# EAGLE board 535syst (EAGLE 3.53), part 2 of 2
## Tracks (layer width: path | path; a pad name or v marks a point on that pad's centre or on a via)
+12V  (via drill 0.61 pad 1.02)
  Top 0.406: 51.73,7.76 51.73,28.72 51.09,29.35 47.28,29.35 46.65,29.98 v46.65,43.64 | v26.01,47.76 26.01,44.27 25.37,43.64 24.74,43.64
  Bottom 0.406: 24.74,43.64 27.28,43.64 33.95,43.64 34.26,43.96 36.49,43.96 36.8,43.64 v46.65,43.64 | D2. 24.74,66.82 24.1,67.45 20.93,67.45 | D2. 24.74,48.4 25.37,47.76 v26.01,47.76 | D2. 22.83,63.64 22.2,63 U$2. 22.2,55.7
A0  (via drill 0.61 pad 1.02)
  Top 0.254: 133.32,4.27 133.32,16.33 132.37,17.29 132.37,21.09 133.32,22.05 133.32,24.27 132.37,25.22 132.37,38.87 133.32,39.83 | 97.76,4.27 94.59,4.27 93.95,4.9 93.95,11.57 93.32,12.21 v93.32,22.05 93.32,34.11 93.95,34.75 v93.95,41.42 | v89.19,44.59 89.19,45.54 88.56,46.18 86.33,46.18 84.43,44.27 75.22,44.27 73.32,46.18 55.85,46.18 54.9,47.13 54.9,60.15 54.27,60.78 48.23,60.78 | v129.51,83.64 129.51,74.75 128.88,74.12 128.88,59.83 127.29,58.24 127.29,41.73 v127.61,41.42
  Bottom 0.254: 133.32,4.27 133.32,4.9 132.69,5.54 104.75,5.54 103.48,4.27 97.76,4.27 | v93.32,22.05 87.6,22.05 | v89.19,44.59 89.19,41.73 93.64,41.73 v93.95,41.42 | v127.61,41.42 131.74,41.42 133.32,39.83 | v129.51,83.64 130.15,83.01 134.59,83.01
A1  (via drill 0.61 pad 1.02)
  Top 0.254: 130.78,4.27 130.78,16.33 129.83,17.29 129.83,21.09 130.78,22.05 131.1,22.36 131.1,34.43 131.74,35.07 131.74,38.87 130.78,39.83 130.78,41.1 131.42,41.73 132.05,41.73 132.69,42.37 132.69,53.16 132.37,53.48 132.37,84.91 133.01,85.55 134.59,85.55 | v101.89,18.24 101.89,4.9 102.53,4.27 105.38,4.27 | v54.27,46.18 54.27,48.72 53.63,49.35 46.33,49.35 45.69,49.99 45.69,60.78 | v51.09,43.64 50.46,43.64 49.82,43 v49.82,36.97 | v45.06,19.19 v45.06,36.97 | v86.65,15.7 86.33,16.01 86.33,18.87 86.97,19.51 87.6,19.51
  Bottom 0.254: v101.89,18.24 93,18.24 91.73,19.51 87.6,19.51 | v54.27,46.18 51.73,46.18 51.09,45.54 v51.09,43.64 | v45.06,36.97 v49.82,36.97 | v45.06,19.19 60.3,19.19 60.93,18.56 60.93,16.33 61.57,15.7 v86.65,15.7 | 130.78,4.27 130.78,3.31 130.15,2.68 108.88,2.68 107.29,4.27 105.38,4.27
A2  (via drill 0.61 pad 1.02)
  Top 0.254: 128.24,4.27 v128.24,13.16 128.24,16.33 127.29,17.29 127.29,20.14 128.24,21.09 128.24,22.05 127.93,22.36 127.93,34.43 127.29,35.07 127.29,39.83 | 127.29,39.83 128.24,39.83 | 48.23,63.32 46.96,64.59 44.42,64.59 43.79,65.23 v43.79,89.68 | v73.63,89.68 73.63,82.69 74.27,82.05 v79.67,82.05 | v97.13,82.37 97.45,82.69 97.45,91.26 98.08,91.9 102.84,91.9 104.11,93.17 v105.7,93.17 | v128.88,88.09 128.88,91.26 128.24,91.9 126.34,91.9 125.7,92.53 v125.7,94.12 125.39,94.44 123.48,94.44 122.85,93.8 122.85,77.29 123.48,76.66 124.75,76.66 125.7,75.71 125.7,74.44 126.66,73.48 126.66,40.46 127.29,39.83
  Bottom 0.254: v128.24,13.16 98.4,13.16 97.76,12.52 97.76,11.89 | v73.63,89.68 v43.79,89.68 | v97.13,82.37 80.3,82.37 79.98,82.05 v79.67,82.05 | v105.7,93.17 108.24,93.17 109.51,94.44 125.39,94.44 v125.7,94.12 | v128.88,88.09 134.59,88.09
A3  (via drill 0.61 pad 1.02)
  Top 0.254: 125.7,4.27 v125.7,11.89 125.7,16.33 124.75,17.29 124.75,20.14 125.7,21.09 125.7,22.05 124.75,23 124.75,38.87 125.7,39.83 v125.7,51.26 | 45.69,63.32 45.69,62.69 46.33,62.05 51.41,62.05 52.04,62.69 v52.04,69.35 | v73.95,69.35 73.95,74.12 74.59,74.75 79.03,74.75 79.67,75.39 v80.62,75.39 | 134.59,90.63 132.37,90.63 131.74,89.99 131.74,75.39 131.42,75.07 v131.42,73.48 131.42,71.9 131.74,71.58 v131.74,51.26
  Bottom 0.254: v125.7,11.89 105.38,11.89 | v52.04,69.35 v73.95,69.35 | v80.62,75.39 97.45,75.39 98.08,74.75 115.86,74.75 116.18,74.44 116.18,73.8 116.5,73.48 v131.42,73.48 | v131.74,51.26 v125.7,51.26
A4  (via drill 0.61 pad 1.02)
  Top 0.254: 123.16,4.27 123.16,16.33 122.21,17.29 122.21,20.46 123.16,21.41 123.16,22.05 v123.16,29.35 123.16,34.43 122.21,35.38 122.21,38.87 123.16,39.83 | v103.8,14.43 103.8,15.06 104.43,15.7 106.65,15.7 107.29,16.33 107.29,28.72 106.65,29.35 105.38,29.35 | 48.23,65.86 49.82,64.28 v50.14,64.28 | v75.86,45.22 v75.86,63 | v91.1,30.62 91.41,30.94 91.41,38.56 91.1,38.87 91.1,42.05 v91.73,42.68
  Bottom 0.254: 97.76,14.43 v103.8,14.43 | v50.14,64.28 53.95,64.28 54.9,65.23 72.36,65.23 73,64.59 73,63.64 73.63,63 v75.86,63 | v75.86,45.22 86.02,45.22 86.97,46.18 88.87,46.18 90.14,44.91 91.1,44.91 91.73,44.27 v91.73,42.68 | v91.1,30.62 98.4,30.62 99.03,29.98 104.75,29.98 105.38,29.35 v123.16,29.35
A5  (via drill 0.61 pad 1.02)
  Top 0.254: 120.62,4.27 v120.62,14.43 120.62,16.33 119.67,17.29 119.67,20.46 120.62,21.41 120.62,22.05 120.62,34.11 119.67,35.07 119.67,38.87 120.62,39.83 | v73.63,52.53 74.27,51.89 v74.27,47.76 | v96.49,48.08 96.49,40.15 97.13,39.51 97.76,39.51
  Bottom 0.254: v120.62,14.43 105.38,14.43 | v73.63,52.53 44.42,52.53 43.79,53.16 43.79,65.23 44.42,65.86 45.69,65.86 | v74.27,47.76 84.75,47.76 85.7,48.72 87.92,48.72 88.56,48.08 v96.49,48.08 96.49,43.96 97.13,43.32 98.08,43.32 99.03,42.37 102.53,42.37 104.11,40.78 119.99,40.78 120.62,40.15 120.62,39.83
A6  (via drill 0.61 pad 1.02)
  Top 0.254: 118.08,4.27 118.08,16.33 117.13,17.29 117.13,20.46 118.08,21.41 118.08,22.05 118.08,34.11 117.13,35.07 117.13,39.51 117.45,39.83 | 117.45,39.83 118.08,39.83 | v77.13,63.96 77.13,61.74 76.49,61.1 76.49,50.94 v76.81,50.62 | 117.45,39.83 117.45,50.62 v117.13,50.94
  Bottom 0.254: 118.08,22.05 118.08,22.68 117.45,23.32 102.84,23.32 101.57,22.05 97.76,22.05 | v77.13,63.96 74.59,63.96 72.68,65.86 53.63,65.86 53,65.23 49.5,65.23 48.87,64.59 47.6,64.59 46.96,65.23 46.96,66.5 46.33,67.13 44.42,67.13 43.79,67.77 43.79,69.04 44.42,69.67 47.6,69.67 48.23,69.04 48.23,68.4 | v76.81,50.62 80.3,50.62 81.57,51.89 94.27,51.89 94.59,52.21 97.76,52.21 98.4,51.57 103.48,51.57 104.11,50.94 v117.13,50.94
A7  (via drill 0.61 pad 1.02)
  Top 0.254: 115.54,4.27 115.54,16.33 114.59,17.29 114.59,20.46 115.54,21.41 115.54,22.05 115.54,33.79 114.59,34.75 114.59,39.83 | 114.59,39.83 115.54,39.83 | v97.45,67.13 97.45,57.61 97.76,57.29 | v114.59,53.48 114.59,39.83
  Bottom 0.254: 115.54,22.05 115.54,21.73 114.91,21.09 106.34,21.09 105.38,22.05 | v97.45,67.13 47.6,67.13 46.33,68.4 45.69,68.4 | v114.59,53.48 108.24,53.48 105.7,56.02 98.4,56.02 97.76,56.65 97.76,57.29
A8  (via drill 0.61 pad 1.02)
  Top 0.254: 118.08,19.51 119.04,20.46 v119.04,34.43 118.08,35.38 118.08,37.29 119.04,38.24 119.04,44.59 118.08,45.54 118.08,55.07 | v95.54,69.99 95.54,64.91 96.49,63.96 96.49,63
  Bottom 0.254: 96.49,63 96.49,60.78 122.21,60.78 122.85,60.15 122.85,57.29 122.21,56.65 118.72,56.65 118.08,56.02 118.08,55.07 | v95.54,69.99 82.52,69.99 82.21,69.67 75.54,69.67 74.27,68.4 51.73,68.4 50.77,69.35 50.77,70.31 50.14,70.94 48.23,70.94 | v119.04,34.43 105.38,34.43
A9  (via drill 0.61 pad 1.02)
  Top 0.254: 121.58,37.29 v121.58,31.89 121.58,20.46 120.62,19.51 | 121.58,37.29 120.62,37.29 | 121.58,37.29 121.58,44.91 120.62,45.86 120.62,55.07 120.62,67.13 119.99,67.77 115.54,67.77 114.91,68.4 v114.91,69.67 | v96.49,71.58 96.49,65.55
  Bottom 0.254: v121.58,31.89 105.38,31.89 | 45.69,70.94 45.69,71.58 46.33,72.21 52.68,72.21 53,71.9 75.22,71.9 75.54,71.58 v96.49,71.58 96.49,70.31 97.13,69.67 105.07,69.67 105.7,70.31 107.29,70.31 107.61,69.99 114.59,69.99 v114.91,69.67
A10  (via drill 0.61 pad 1.02)
  Top 0.254: 128.88,37.29 128.88,23.95 129.2,23.63 129.2,20.46 128.24,19.51 | 128.88,37.29 128.24,37.29 | v108.24,57.61 107.92,57.93 107.92,58.88 107.61,59.19 107.61,63.32 v107.92,63.64 | v51.73,73.16 v51.73,70.94 | v74.9,70.94 74.9,73.48 75.54,74.12 v79.67,74.12 | v94.59,74.44 94.59,68.4 94.91,68.08 v94.91,63.96 | 128.88,37.29 129.2,37.61 129.2,43 128.56,43.64 128.56,54.75 128.24,55.07
  Bottom 0.254: 105.38,36.97 105.38,36.02 106.02,35.38 126.34,35.38 128.24,37.29 | v108.24,57.61 107.92,57.93 107.92,58.88 107.29,59.51 99.99,59.51 99.35,58.88 95.54,58.88 94.91,59.51 v94.91,63.96 97.13,63.96 97.76,63.32 98.72,63.32 99.03,63 | v107.92,63.64 108.24,63.96 111.42,63.96 112.05,63.32 112.05,62.05 112.69,61.42 115.23,61.42 115.86,62.05 141.26,62.05 141.9,61.42 141.9,54.75 141.26,54.11 128.88,54.11 128.24,54.75 128.24,55.07 | v51.73,73.16 51.41,73.48 48.23,73.48 | v51.73,70.94 52.04,71.26 74.59,71.26 v74.9,70.94 | v79.67,74.12 94.27,74.12 v94.59,74.44
A11  (via drill 0.61 pad 1.02)
  Top 0.254: 123.16,19.51 124.12,20.46 124.12,34.43 123.16,35.38 123.16,37.29 124.12,38.24 124.12,40.15 123.8,40.46 123.8,45.54 123.16,46.18 123.16,55.07 | v100.62,39.51 100.62,41.1 100.94,41.42 100.94,56.34 101.57,56.97 v101.57,63 101.57,65.55 | 45.69,73.48 46.96,72.21 48.87,72.21 49.5,71.58 49.5,66.5 v49.82,66.18
  Bottom 0.254: v100.62,39.51 105.38,39.51 105.7,39.83 109.19,39.83 110.15,38.87 122.53,38.87 123.16,38.24 123.16,37.29 | v49.82,66.18 50.14,66.5 96.81,66.5 97.76,65.55 97.76,64.59 98.4,63.96 99.67,63.96 100.62,63 v101.57,63
A12  (via drill 0.61 pad 1.02)
  Top 0.254: 113,4.27 113,16.01 112.05,16.97 112.05,20.46 113,21.41 113,22.05 113,33.79 112.05,34.75 112.05,38.87 113,39.83 v113,44.59 | v103.48,63.96 103.48,49.04 104.11,48.4 106.02,48.4 106.65,47.76 106.65,45.22 106.02,44.59 105.38,44.59 | v50.46,68.08 50.46,75.39 49.82,76.02 48.23,76.02
  Bottom 0.254: v103.48,63.96 100.62,63.96 99.03,65.55 98.4,66.18 98.4,67.45 97.76,68.08 82.52,68.08 81.57,69.04 75.86,69.04 74.59,67.77 50.77,67.77 v50.46,68.08 | v113,44.59 105.38,44.59
A13  (via drill 0.61 pad 1.02)
  Top 0.254: 115.54,19.51 116.5,20.46 116.5,33.79 115.54,34.75 115.54,37.29 116.5,38.24 116.5,44.27 115.54,45.22 v115.54,47.13 115.54,55.07 | 105.38,47.13 103.48,47.13 102.84,47.76 102.84,56.65 102.53,56.97 102.53,67.13 101.57,68.08 100.62,69.04 100.62,71.26 99.99,71.9 v99.67,71.9
  Bottom 0.254: v99.67,71.9 97.76,71.9 97.13,72.53 94.59,72.53 94.27,72.21 75.86,72.21 75.54,72.53 60.93,72.53 60.3,73.16 60.3,74.12 59.66,74.75 46.33,74.75 45.69,75.39 45.69,76.02 | 105.38,47.13 v115.54,47.13
A14  (via drill 0.61 pad 1.02)
  Top 0.254: 109.51,22.05 109.51,5.22 110.46,4.27 | 109.51,22.05 110.46,22.05 | v113,49.67 113,55.07 | v104.43,61.74 104.11,61.42 104.11,50.3 104.75,49.67 105.38,49.67 107.61,49.67 108.24,49.04 108.24,46.18 107.92,45.86 107.92,22.68 108.56,22.05 109.51,22.05 | v53,70.31 53,77.93 52.36,78.56 48.23,78.56 | v73,70.31 73,76.02 73.63,76.66 v79.67,76.66 | v97.45,76.66 97.45,69.67 99.03,68.08
  Bottom 0.254: 105.38,49.67 v113,49.67 | v104.43,61.74 104.43,65.86 103.8,66.5 101.26,66.5 100.94,66.18 99.67,66.18 99.03,66.82 99.03,68.08 | v73,70.31 v53,70.31 | v97.45,76.66 v79.67,76.66
A15  (via drill 0.61 pad 1.02)
  Top 0.254: v108.24,70.94 108.24,65.86 106.97,64.59 106.97,58.24 107.29,57.93 107.29,52.85 106.65,52.21 105.38,52.21 | v72.68,88.72 72.68,80.15 73.32,79.52 79.67,79.52 80.3,78.88 v80.3,77.93 | v100.62,77.29 100.62,72.85 101.57,71.9 101.57,70.63 | J3. v45.69,88.72
  Bottom 0.254: v108.24,70.94 105.07,70.94 104.75,70.63 101.57,70.63 | v45.69,88.72 v72.68,88.72 | v80.3,77.93 80.62,77.61 98.08,77.61 98.4,77.29 v100.62,77.29
ALE  (via drill 0.61 pad 1.02)
  Top 0.254: v95.86,74.44 95.86,74.75 95.22,75.39 93.95,75.39 93.32,74.75 93.32,68.08 93,67.77 v93,58.24 | v94.91,58.24 94.59,57.93 94.59,56.02 94.91,55.7 v94.91,51.26 | v107.29,48.4 107.29,31.25 106.65,30.62 104.75,30.62 104.11,29.98 v104.11,28.4 | v96.81,28.08 97.13,28.08 97.76,27.45 97.76,24.59
  Bottom 0.254: v95.86,74.44 96.18,74.12 100.62,74.12 101.57,73.16 | v94.91,58.24 v93,58.24 | v94.91,51.26 95.22,50.94 98.4,50.94 99.03,50.3 102.84,50.3 104.75,48.4 v107.29,48.4 | v96.81,28.08 103.8,28.08 v104.11,28.4
CS_E^2  (via drill 0.61 pad 1.02)
  Top 0.254: v100.3,58.56 100.3,43 99.67,42.37 99.03,42.37 98.4,43 98.4,43.96 97.76,44.59
  Bottom 0.254: v100.3,58.56 106.65,58.56 107.29,57.93 107.29,55.39 108.56,54.11 113.32,54.11 113.64,54.43 114.91,54.43 115.86,53.48 145.07,53.48 145.39,53.8 148.56,53.8
CS_PIO  (via drill 0.61 pad 1.02)
  Top 0.254: v94.27,45.22 94.27,43.32 93,42.05 93,38.87 92.68,38.56 92.68,23.63 92.05,23 92.05,17.6 91.41,16.97 89.51,16.97 88.87,16.33 88.87,15.06 88.24,14.43 87.6,14.43
  Bottom 0.254: v94.27,45.22 94.27,42.68 94.91,42.05 97.76,42.05
CS_PROM  (via drill 0.61 pad 1.02)
  Top 0.254: v98.72,53.48 99.03,53.16 99.03,47.76 98.4,47.13 97.76,47.13 | v130.78,52.53 130.78,55.07
  Bottom 0.254: v130.78,52.53 107.92,52.53 106.97,53.48 v98.72,53.48
CS_RAM  (via drill 0.61 pad 1.02)
  Top 0.254: v99.67,30.94 99.67,33.79 99.03,34.43 97.76,34.43 | v142.53,30.62 142.53,44.91 v141.9,45.54
  Bottom 0.254: v99.67,30.94 99.99,30.62 v142.53,30.62 | v141.9,45.54 142.53,46.18 148.56,46.18
CS_RTC  (via drill 0.61 pad 1.02)
  Top 0.254: v104.11,45.86 104.11,43.32 105.38,42.05 | v134.28,45.86 134.28,72.85 133.32,73.8 133.32,77.29 133.96,77.93 134.59,77.93
  Bottom 0.254: v104.11,45.86 v134.28,45.86
GND  (via drill 0.61 pad 1.02)
  Top 0.406: 24.74,46.18 v14.58,46.18 7.91,46.18 7.28,45.54 7.28,21.41 6.64,20.78 6.01,20.78 | 30.77,77.61 30.77,84.91 30.14,85.55 16.48,85.55 15.85,84.91 15.85,80.79 16.48,80.15 17.12,80.15 17.12,77.61 18.39,76.34 C12. | v92.37,73.16 92.37,66.5 91.41,65.55 | v105.38,62.69 105.7,62.37 105.7,57.61 105.38,57.29 | 107.92,72.85 108.56,72.85 109.51,71.9 109.51,63 109.19,62.69 | R1. 156.18,62.69 155.55,63.32 155.55,66.5 154.6,67.45 154.6,77.29 153.96,77.93 151.1,77.93 | 143.48,39.83 143.48,49.99 142.53,50.94 142.53,63.32 143.17,63.96 BAT1. | v121.26,96.98 120.62,96.34 120.62,84.28 120.94,83.96 120.94,83.33 v121.26,83.01 121.58,82.69 121.58,77.61 121.26,77.29 121.26,69.35 120.62,68.72 118.72,68.72 118.08,69.35 118.08,72.21 117.45,72.85 C15. | C16. 90.46,32.84 90.46,43.64 90.46,46.18 90.46,49.99 v90.46,53.16 | v105.38,27.76 105.38,24.59 | 95.22,14.43 95.54,14.74 95.54,22.36 96.49,23.32 96.49,26.49 95.54,27.45 C7. | 143.48,4.27 143.48,16.33 142.21,17.6 142.21,20.14 143.48,21.41 143.48,22.05 v143.48,27.76
  Bottom 0.254: 94.59,29.03 95.22,28.4 C7.
  Bottom 0.406: 6.01,20.78 6.01,18.87 6.64,18.24 15.21,18.24 16.48,16.97 17.75,15.7 17.75,2.36 | 24.74,46.18 27.28,46.18 27.91,46.81 53,46.81 53.63,47.45 53.63,50.62 54.27,51.26 74.59,51.26 75.22,51.89 75.22,53.8 | 15.85,2.36 17.75,2.36 | 17.75,2.36 46.33,2.36 46.65,2.68 | C13. 30.14,73.8 30.77,74.44 30.77,77.61 | X2. 5.69,79.52 6.32,80.15 17.12,80.15 | C12. 15.21,67.45 14.58,66.82 14.58,63.64 v14.58,46.18 | v92.37,73.16 99.03,73.16 99.99,73.16 101.26,71.9 106.97,71.9 107.92,72.85 109.19,71.58 113.32,71.58 113.96,72.21 114.91,72.21 C15. | 109.19,62.69 108.88,62.37 105.7,62.37 v105.38,62.69 | 156.18,62.69 154.6,64.28 143.8,64.28 BAT1. | 151.1,77.93 151.1,78.56 150.47,79.2 143.48,79.2 142.85,79.83 137.77,79.83 137.13,80.47 137.13,81.1 136.5,81.74 129.2,81.74 128.24,82.69 128.24,83.64 127.61,84.28 126.34,84.28 125.07,83.01 124.43,83.01 v121.26,83.01 | v121.26,96.98 118.08,96.98 | 87.6,16.97 91.41,16.97 92.05,16.33 92.05,15.06 92.68,14.43 95.22,14.43 | 75.22,53.8 C10. | 75.22,53.8 79.03,53.8 M1. v90.46,53.16 | 94.59,29.03 90.46,29.03 89.83,29.67 89.83,32.21 C16. | C7. 95.86,26.81 97.76,26.81 98.08,27.13 104.75,27.13 v105.38,27.76 v143.48,27.76 145.07,27.76 | 143.48,4.27 143.48,2.36 142.85,1.73 105.38,1.73 | 145.07,27.76 148.56,27.76 | 145.07,27.76 145.07,39.19 144.44,39.83 143.48,39.83
INT0  (via drill 0.61 pad 1.02)
  Top 0.254: v72.05,93.17 71.73,92.85 71.73,69.04 72.36,68.4 74.59,68.4 75.54,69.35 77.44,69.35 78.71,70.63
  Bottom 0.254: v72.05,93.17 71.41,93.8 59.98,93.8 59.35,94.44
INT1  (via drill 0.61 pad 1.02)
  Top 0.254: 76.17,68.08 76.49,68.08 77.13,67.45 77.13,65.23 76.49,64.59 67.92,64.59 67.28,65.23 v67.28,85.55 67.28,92.21 66.65,92.85 63.47,92.85 62.84,93.49 62.84,96.34 62.2,96.98 J4.
  Bottom 0.254: v67.28,85.55 74.59,85.55 75.86,84.28 79.67,84.28 80.3,83.64 97.13,83.64 99.03,81.74 102.21,81.74 102.53,81.42 103.8,81.42 104.11,81.74 112.37,81.74 113,81.1 113,80.47
MODE  (via drill 0.61 pad 1.02)
  Top 0.254: v99.35,43.64 99.67,43.96 99.67,54.11 99.03,54.75 97.76,54.75 | 148.56,16.33 154.28,16.33 154.91,16.97 154.91,39.19 156.18,40.46 156.18,43.64
  Bottom 0.254: v99.35,43.64 99.67,43.32 106.65,43.32 107.29,42.68 146.34,42.68 146.66,42.37 155.55,42.37 156.18,43 156.18,43.64
N$1  (via drill 0.61 pad 1.02)
  Top 0.254: v124.43,63.96 124.43,75.39
  Bottom 0.254: C8. 114.91,63.32 117.45,63.32 118.08,63.96 v124.43,63.96
N$2  (via drill 0.61 pad 1.02)
  Top 0.254: 148.56,38.56 150.15,38.56 150.79,39.19 150.79,49.99 151.42,50.62 153.01,50.62 153.64,51.26 R12. v153.64,65.86 | v111.73,66.5 111.73,89.68 111.1,90.31 108.56,90.31 107.92,89.68 R3.
  Bottom 0.254: v153.64,65.86 117.45,65.86 R10. v111.73,66.5
N$3
  Bottom 0.254: 148.56,56.34 151.1,56.34 151.74,55.7 151.74,51.26 153.64,49.35 153.64,43.64
N$4  (via drill 0.61 pad 1.02)
  Top 0.254: v116.5,48.72 116.18,49.04 116.18,52.85 116.5,53.16 116.5,64.28 v115.23,65.55
  Bottom 0.254: v115.23,65.55 107.29,65.55 106.65,66.18 106.65,66.5 | v116.5,48.72 148.56,48.72
N$5
  Top 0.254: 130.78,19.51 131.1,19.51 131.74,18.87 131.74,2.36 132.37,1.73 R13. 145.39,2.36 145.39,16.33 146.66,17.6 146.66,39.19 147.29,39.83 147.29,41.73 147.93,42.37 149.2,42.37 149.83,43 149.83,58.24 149.2,58.88 T3.
N$6  (via drill 0.61 pad 1.02)
  Top 0.254: v145.39,41.42 v145.39,51.26 v145.39,69.04
  Bottom 0.254: v145.39,41.42 135.23,41.42 134.59,40.78 134.59,39.19 133.96,38.56 131.42,38.56 130.78,37.92 130.78,37.29 | v145.39,51.26 T2. | v145.39,69.04 R11.
N$7  (via drill 0.61 pad 1.02)
  Top 0.254: v151.1,82.37 151.1,85.55
  Bottom 0.254: v151.1,82.37 146.02,82.37 144.75,81.1 144.75,80.47
N$8
  Top 0.254: C3. 152.37,80.47 153.01,81.1 153.01,89.99 152.37,90.63 144.75,90.63
N$9
  Top 0.254: R15. 94.59,23.95 94.59,16.33 93.95,15.7 93.95,13.16 95.22,11.89 T4.
  Bottom 0.254: 72.36,14.43 85.06,14.43 86.33,13.16 94.59,13.16 95.22,12.52 T4.
N$10
  Bottom 0.406: 19.66,83.64 19.02,83.64 18.39,83.01 18.39,77.93 17.12,76.66 R7. 17.12,69.35 17.75,68.72 19.02,68.72 19.66,68.08 19.66,66.82 19.02,66.18 17.75,66.18 17.12,65.55 17.12,56.02
N$11
  Bottom 0.254: 144.75,77.93 147.29,77.93
N$12
  Top 0.254: 144.75,83.01 146.66,83.01 147.29,82.37 C1.
N$13
  Bottom 0.254: 144.75,85.55 147.29,85.55
N$14
  Bottom 0.254: 144.75,88.09 C2.
N$15  (via drill 0.61 pad 1.02)
  Top 0.254: v158.09,19.51 v158.09,83.64
  Bottom 0.254: v158.09,83.64 157.45,84.28 143.48,84.28 142.21,85.55 137.13,85.55 | 148.56,19.51 v158.09,19.51
N$16  (via drill 0.61 pad 1.02)
  Top 0.254: 137.13,83.01 137.13,83.96 138.4,85.23 140.94,85.23 141.58,84.6 141.58,60.78 141.9,60.47 v141.9,47.45 | v151.74,47.45 151.74,42.37 153.01,41.1 153.01,22.68 152.37,22.05 148.56,22.05
  Bottom 0.254: v151.74,47.45 v141.9,47.45
N$17
  Bottom 0.254: 16.48,19.51 16.48,20.14 15.85,20.78 8.86,20.78 8.23,21.41 8.23,22.68 7.59,23.32 6.01,23.32 5.37,23.32 4.1,24.59 2.83,24.59 2.2,23.95 2.2,16.97 2.83,16.33 5.05,16.33 5.69,15.7 R6.
N$18
  Top 0.254: 90.14,14.43 92.05,14.43 92.68,13.79 92.68,10.62
N$19  (via drill 0.61 pad 1.02)
  Top 0.254: v119.04,76.02 118.72,76.34 118.72,82.05 118.4,82.37 118.4,83.64 117.77,84.28 114.27,84.28 JP3.
  Bottom 0.254: v119.04,76.02 123.48,76.02 124.12,76.66 129.83,76.66 130.47,76.02 133.96,76.02 134.59,75.39 | R16. JP3.
N$21  (via drill 0.61 pad 1.02)
  Top 0.254: v114.27,55.39 114.27,54.75 113.64,54.11 113.64,51.26 113.96,50.94 113.96,20.46 113,19.51 | v111.42,56.02 111.73,56.34 111.73,58.88
  Bottom 0.254: v114.27,55.39 113.64,56.02 v111.42,56.02
N$22  (via drill 1.93 pad 2.54)
  other vias: 157.45,3
N$23
  Top 0.254: 19.66,69.99 19.66,76.66 18.39,77.93 18.39,83.01 17.75,83.64 JP1.
N$24
  Bottom 0.254: 22.2,83.64 27.6,83.64 28.23,83.01 28.23,70.63 27.6,69.99 22.2,69.99
N$25  (via drill 1.93 pad 2.54)
  other vias: 157.45,96.98
N$26  (via drill 1.93 pad 2.54)
  other vias: 2.51,3
N$27  (via drill 1.93 pad 2.54)
  other vias: 2.51,96.98
N$28  (via drill 2.54 pad 3.81)
  other vias: 6.96,58.56
N$29  (via drill 2.54 pad 3.81)
  other vias: 32.36,58.56
N$34  (via drill 0.61 pad 1.02)
  Top 0.254: v91.73,52.85 91.73,44.91 C5.
  Bottom 0.254: 91.1,57.29 90.78,56.97 84.75,56.97 Q1. | 91.1,57.29 91.1,58.56 91.73,59.19 92.37,59.19 93,59.83 93,64.91 93.64,65.55 93.95,65.55 | v91.73,52.85 92.37,53.48 95.86,53.48 96.49,54.11 96.49,56.65 95.86,57.29 91.1,57.29
N$35  (via drill 0.61 pad 1.02)
  Top 0.254: 93.95,63 v93.95,55.39 93.95,50.62 94.27,50.3 94.27,46.81 93.64,46.18 C6.
  Bottom 0.254: v93.95,55.39 90.46,55.39 90.14,55.07 82.52,55.07 81.25,56.34 79.03,56.34
P00  (via drill 0.61 pad 1.02)
  Top 0.254: v104.11,85.23 104.11,79.83 103.8,79.52 103.8,76.97 104.11,76.66 104.11,75.07 103.48,74.44 102.21,74.44 101.57,75.07 101.57,75.71 | 135.86,4.27 135.86,16.33 134.91,17.29 134.91,21.09 135.86,22.05 135.86,24.27 134.91,25.22 134.91,39.51 135.23,39.83 | 135.23,39.83 135.86,39.83 | v74.27,7.13 74.27,16.33 73.63,16.97 72.36,16.97 | v139.04,84.28 139.04,72.21 138.4,71.58 135.55,71.58 134.91,70.94 134.91,53.8 135.23,53.48 135.23,39.83
  Bottom 0.254: 64.43,21.41 64.43,17.6 65.06,16.97 72.36,16.97 | v104.11,85.23 114.91,85.23 115.86,84.28 125.07,84.28 126.34,85.55 IC10.4 129.83,85.55 131.1,84.28 v139.04,84.28 | 135.86,4.27 135.86,6.81 135.23,7.44 107.29,7.44 106.65,8.08 103.8,8.08 102.53,6.81 97.76,6.81 89.19,6.81 87.92,8.08 85.06,8.08 84.43,7.44 74.59,7.44 v74.27,7.13
P01  (via drill 0.61 pad 1.02)
  Top 0.254: v104.75,77.93 105.07,78.24 105.07,86.5 v105.38,86.82 | 138.4,4.27 138.4,16.33 137.45,17.29 137.45,21.09 138.4,22.05 138.4,24.27 137.45,25.22 137.45,39.83 | 137.45,39.83 138.4,39.83 | v75.22,4.59 75.22,18.87 74.59,19.51 72.36,19.51 | v130.78,57.61 130.78,72.53 130.47,72.85 130.47,86.5 129.83,87.13 128.24,87.13 127.29,88.09 IC10.3 | 137.45,39.83 v137.45,57.61
  Bottom 0.254: J9. 61.89,22.05 62.52,22.68 67.28,22.68 67.92,22.05 67.92,20.14 68.55,19.51 72.36,19.51 | v104.75,77.93 104.75,77.29 104.11,76.66 101.26,76.66 100.3,75.71 99.03,75.71 | v105.38,86.82 126.34,86.82 126.97,87.45 IC10.3 | 138.4,4.27 137.45,3.31 135.23,3.31 134.59,3.95 134.59,6.17 133.96,6.81 105.38,6.81 104.43,6.81 103.16,5.54 85.38,5.54 84.75,4.9 75.54,4.9 v75.22,4.59 | v137.45,57.61 v130.78,57.61
P02  (via drill 0.61 pad 1.02)
  Top 0.254: v109.19,89.36 v109.19,78.88 | 140.94,4.27 v140.94,10.62 140.94,16.33 139.99,17.29 139.99,21.09 140.94,22.05 140.94,24.27 139.99,25.22 139.99,38.87 140.94,39.83 140.94,43 139.99,43.96 v139.99,63 | v76.17,12.84 76.17,21.41 75.54,22.05 72.36,22.05 | v127.93,63 127.93,74.44 128.24,74.75 128.24,86.18 127.61,86.82 126.34,86.82 125.7,87.45 125.7,89.99 126.34,90.63 IC10.2
  Bottom 0.254: 64.43,23.95 68.24,23.95 68.87,23.32 68.87,22.68 69.51,22.05 72.36,22.05 | 101.57,78.24 103.48,78.24 104.11,78.88 v109.19,78.88 | v109.19,89.36 126.34,89.36 126.97,89.99 IC10.2 | v140.94,10.62 104.75,10.62 103.48,9.35 97.76,9.35 97.13,8.71 90.14,8.71 88.24,10.62 87.29,10.62 85.06,12.84 v76.17,12.84 75.86,12.84 | v139.99,63 v127.93,63
P03  (via drill 0.61 pad 1.02)
  Top 0.254: 143.48,19.51 144.44,20.46 144.44,34.11 143.48,35.07 143.48,37.29 144.44,38.24 144.44,55.07 | 144.44,55.07 143.48,55.07 | v83.48,80.15 83.48,69.67 82.84,69.04 80.94,69.04 80.3,68.4 80.3,61.74 80.94,61.1 88.56,61.1 89.19,60.47 v89.19,56.02 | v95.54,56.34 95.86,56.02 98.4,56.02 99.03,56.65 99.03,59.51 v98.72,59.83 | v119.67,63 v119.67,59.83 | 144.44,55.07 144.75,55.39 144.75,66.5 142.85,68.4 142.85,91.26 142.21,91.9 132.69,91.9 131.42,93.17 IC10.1 | v89.19,8.08 84.43,8.08 83.79,8.71 83.79,23.95 83.16,24.59 72.36,24.59
  Bottom 0.254: 61.89,23.95 61.89,24.59 62.52,25.22 68.87,25.22 69.51,24.59 72.36,24.59 | v83.48,80.15 81.25,80.15 80.62,79.52 80.62,78.88 81.25,78.24 99.03,78.24 | v89.19,56.02 89.51,56.34 v95.54,56.34 | v98.72,59.83 99.03,60.15 119.35,60.15 v119.67,59.83 | v119.67,63 125.7,63 126.66,63.96 141.26,63.96 143.48,61.74 143.48,55.07 | 143.48,19.51 143.48,9.98 142.85,9.35 105.38,9.35 104.75,8.71 101.89,8.71 101.26,8.08 v89.19,8.08
P04  (via drill 0.61 pad 1.02)
  Top 0.254: 140.94,19.51 140.94,20.46 141.9,21.41 141.9,24.59 141.26,25.22 141.26,34.11 140.94,34.43 140.94,37.29 141.9,38.24 141.9,43 140.94,43.96 140.94,55.07 | v106.97,80.79 106.97,75.07 105.38,73.48 105.38,64.91 v105.7,64.59 | v136.5,56.65 v136.5,64.91
  Bottom 0.254: 64.43,26.49 71.73,26.49 72.36,27.13 74.9,27.13 75.54,26.49 75.54,21.41 76.17,20.78 85.38,20.78 | 85.38,20.78 85.38,19.19 86.33,18.24 91.73,18.24 93,16.97 97.76,16.97 | v105.7,64.59 116.5,64.59 117.13,65.23 136.18,65.23 v136.5,64.91 | v136.5,56.65 140.31,56.65 140.94,56.02 140.94,55.07 | v106.97,80.79 101.57,80.79 | 85.38,20.78 105.7,20.78 106.02,20.46 116.18,20.46 116.81,21.09 140.31,21.09 140.94,20.46 140.94,19.51
P05  (via drill 0.61 pad 1.02)
  Top 0.254: 138.4,19.51 138.72,19.51 139.36,20.14 139.36,34.11 138.4,35.07 138.4,37.29 139.36,38.24 139.36,43 138.4,43.96 138.4,55.07 v138.4,69.99 | v114.91,79.83 115.54,79.2 115.54,74.44 116.18,73.8 118.08,73.8 118.72,73.16 118.72,70.63 v119.35,69.99 | v103.8,33.48 103.8,31.57 102.84,30.62 102.84,24.91 103.48,24.27 103.48,17.6 104.11,16.97 105.38,16.97
  Bottom 0.254: 61.89,26.49 61.89,27.13 62.52,27.76 68.87,27.76 69.51,28.4 69.51,29.03 70.14,29.67 72.36,29.67 82.21,29.67 82.84,30.3 82.84,32.84 83.48,33.48 88.56,33.48 88.87,33.79 95.86,33.79 96.49,33.16 103.48,33.16 v103.8,33.48 | 99.03,80.79 100.3,80.79 101.26,79.83 111.42,79.83 112.05,79.2 114.27,79.2 v114.91,79.83 | v138.4,69.99 v119.35,69.99 | 138.4,19.51 138.4,17.6 137.77,16.97 105.38,16.97
P06  (via drill 0.61 pad 1.02)
  Top 0.254: 135.86,19.51 136.18,19.51 136.82,20.14 136.82,34.11 135.86,35.07 135.86,37.29 136.82,38.24 136.82,43 135.86,43.96 135.86,55.07 | v117.77,81.74 118.08,81.42 118.08,75.07 v118.4,74.75 | v122.85,74.44 123.48,73.8 123.48,56.97 v123.8,56.65 | v96.81,15.7 96.49,16.01 96.49,18.24 97.76,19.51 | v100.62,35.7 v100.62,19.51
  Bottom 0.254: 64.43,29.03 67.92,29.03 68.55,29.67 68.55,31.57 69.19,32.21 72.36,32.21 80.3,32.21 80.94,32.84 80.94,35.38 81.57,36.02 94.27,36.02 94.59,35.7 v100.62,35.7 | v117.77,81.74 115.54,81.74 114.91,82.37 114.91,83.64 114.27,84.28 107.29,84.28 106.34,83.33 101.57,83.33 | v118.4,74.75 118.72,74.44 v122.85,74.44 | v123.8,56.65 134.28,56.65 135.86,55.07 | v96.81,15.7 108.56,15.7 109.19,16.33 139.04,16.33 139.67,16.97 139.67,19.82 139.04,20.46 136.82,20.46 135.86,19.51 | v100.62,19.51 97.76,19.51
P07  (via drill 0.61 pad 1.02)
  Top 0.254: 133.32,19.51 133.64,19.51 134.28,20.14 134.28,34.11 133.32,35.07 133.32,37.29 134.28,38.24 134.28,42.68 133.32,43.64 133.32,55.07 v133.32,70.94 | v103.16,75.71 v103.16,82.37 | v114.27,70.94 v114.27,75.71 | v101.89,37.29 101.89,32.21 101.26,31.57 101.26,23.63 101.89,23 v101.89,19.51
  Bottom 0.254: 61.89,29.03 61.89,29.67 62.52,30.3 66.65,30.3 67.28,30.94 67.28,34.11 67.92,34.75 72.36,34.75 78.4,34.75 79.03,35.38 79.03,37.92 79.67,38.56 93.64,38.56 93.95,38.24 98.08,38.24 99.03,37.29 v101.89,37.29 | v103.16,82.37 99.99,82.37 99.03,83.33 | v114.27,75.71 v103.16,75.71 | v133.32,70.94 v114.27,70.94 | 133.32,19.51 133.32,18.56 132.69,17.92 109.51,17.92 107.92,19.51 105.38,19.51 v101.89,19.51
P10
  Bottom 0.254: 65.38,53.8 70.46,53.8 71.09,54.43 71.09,56.97 71.73,57.61 89.83,57.61 90.46,58.24 90.46,64.91 89.83,65.55 88.87,65.55
P11
  Bottom 0.254: J8. 62.84,54.43 63.47,55.07 69.82,55.07 70.46,55.7 70.46,57.61 71.09,58.24 88.24,58.24 88.87,58.88 88.87,63
P12
  Bottom 0.254: 65.38,56.34 69.19,56.34 69.82,56.97 69.82,58.24 70.46,58.88 86.97,58.88 87.6,59.51 87.6,64.91 86.97,65.55 86.33,65.55
P13
  Bottom 0.254: 62.84,56.34 62.84,56.97 63.47,57.61 68.55,57.61 69.19,58.24 69.19,58.88 69.82,59.51 85.7,59.51 86.33,60.15 86.33,63
P14
  Bottom 0.254: 65.38,58.88 67.92,58.88 69.19,60.15 84.43,60.15 85.06,60.78 85.06,64.91 84.43,65.55 83.79,65.55
P15
  Bottom 0.254: 62.84,58.88 62.84,59.51 63.47,60.15 67.92,60.15 68.55,60.78 83.16,60.78 83.79,61.42 83.79,63
P16
  Bottom 0.254: 65.38,61.42 81.89,61.42 82.52,62.05 82.52,64.91 81.89,65.55 81.25,65.55
P17
  Bottom 0.254: 62.84,61.42 62.84,62.05 63.47,62.69 66.01,62.69 66.65,62.05 80.62,62.05 81.25,62.69 81.25,63
P40
  Bottom 0.254: 83.16,96.98 88.24,96.98 88.87,96.34 88.87,88.41
P41
  Bottom 0.254: J7. 84.43,94.44 85.06,93.8 85.06,87.77 85.7,87.13 88.24,87.13 88.87,86.5 88.87,85.86
P42
  Bottom 0.254: 80.62,96.98 80.62,96.34 81.25,95.71 85.7,95.71 86.33,95.07 86.33,88.41
P43
  Bottom 0.254: 80.62,94.44 80.62,93.8 81.25,93.17 83.16,93.17 83.79,92.53 83.79,88.41
P44
  Bottom 0.254: 78.08,96.98 78.71,96.98 79.35,96.34 79.35,92.85 79.98,92.21 81.89,92.21 82.52,91.58 82.52,86.5 83.16,85.86 83.79,85.86
P45
  Bottom 0.254: 78.08,94.44 78.08,91.9 78.71,91.26 80.62,91.26 81.25,90.63 81.25,88.41
P46
  Bottom 0.254: 75.54,96.98 76.17,96.98 76.81,96.34 76.81,90.94 77.44,90.31 79.35,90.31 79.98,89.68 79.98,86.5 80.62,85.86 81.25,85.86
P47
  Bottom 0.254: 75.54,94.44 75.54,89.04 76.17,88.41 78.71,88.41
P50
  Bottom 0.254: 94.59,94.44 92.05,94.44 91.41,93.8 91.41,88.41
P51
  Bottom 0.254: J5. 95.22,96.98 95.86,96.34 95.86,93.8 95.22,93.17 93.32,93.17 92.68,92.53 92.68,86.5 93.32,85.86 93.95,85.86
P52
  Bottom 0.254: 97.13,94.44 97.13,92.85 96.49,92.21 94.59,92.21 93.95,91.58 93.95,88.41
P53
  Bottom 0.254: 97.13,96.98 97.76,96.98 98.4,96.34 98.4,91.9 97.76,91.26 95.86,91.26 95.22,90.63 95.22,86.5 95.86,85.86 96.49,85.86
P54
  Bottom 0.254: 99.67,94.44 99.67,90.94 99.03,90.31 97.13,90.31 96.49,89.68 96.49,88.41
P55
  Bottom 0.254: 99.67,96.98 100.3,96.98 100.94,96.34 100.94,89.99 100.3,89.36 98.4,89.36 97.76,88.72 97.76,86.5 98.4,85.86 99.03,85.86
P56
  Bottom 0.254: 102.21,94.44 102.21,89.04 101.57,88.41 99.03,88.41
P57
  Bottom 0.254: 102.21,96.98 102.84,96.98 103.48,96.34 103.48,86.5 102.84,85.86 101.57,85.86
P60
  Bottom 0.254: 65.38,75.71 65.38,73.8 66.01,73.16 76.17,73.16
P61
  Bottom 0.254: J10. 62.84,76.34 63.47,76.97 67.28,76.97 67.92,76.34 67.92,75.07 68.55,74.44 78.08,74.44 78.71,75.07 78.71,75.71
P62
  Bottom 0.254: 65.38,78.24 68.55,78.24 69.19,77.61 69.19,76.34 69.82,75.71 76.17,75.71
P63
  Bottom 0.254: 62.84,78.24 62.84,78.88 63.47,79.52 69.82,79.52 70.46,78.88 70.46,77.61 71.09,76.97 78.08,76.97 78.71,77.61 78.71,78.24
P64
  Bottom 0.254: 65.38,80.79 71.09,80.79 71.73,80.15 71.73,78.88 72.36,78.24 76.17,78.24
P65
  Bottom 0.254: 62.84,80.79 62.84,81.42 63.47,82.05 72.36,82.05 73,81.42 73,80.15 73.63,79.52 78.08,79.52 78.71,80.15 78.71,80.79
P66
  Bottom 0.254: 65.38,83.33 73.32,83.33 73.95,82.69 73.95,81.42 74.59,80.79 76.17,80.79
P67
  Bottom 0.254: 62.84,83.33 62.84,83.96 63.47,84.6 74.27,84.6 74.9,83.96 74.9,82.69 75.54,82.05 78.08,82.05 78.71,82.69 78.71,83.33
PA0
  Top 0.254: 27.28,10.62 27.28,11.25 26.64,11.89 19.34,11.89 18.71,12.52 18.71,25.22 18.07,25.86 14.58,25.86 13.94,26.49 13.94,27.13
  Bottom 0.254: 6.01,28.4 9.5,28.4 10.77,27.13 13.94,27.13 | 27.28,10.62 53.95,10.62 54.58,9.98 54.58,8.71 55.22,8.08 83.79,8.08 85.06,9.35 87.6,9.35
PA1
  Bottom 0.254: 3.47,28.4 3.47,29.03 4.1,29.67 9.82,29.67 11.09,28.4 15.85,28.4 16.48,29.03 16.48,29.67 18.07,29.67 18.71,29.03 18.71,11.25 19.34,10.62 24.74,10.62 24.74,6.17 25.37,5.54 84.11,5.54 85.38,6.81 87.6,6.81
PA2  (via drill 0.61 pad 1.02)
  Top 0.254: 27.28,13.16 27.28,13.79 26.64,14.43 20.29,14.43 19.66,15.06 19.66,27.76 19.02,28.4 15.85,28.4 14.58,29.67 13.94,29.67 | v54.9,13.16 54.9,3.63 55.54,3 86.33,3 87.6,4.27
  Bottom 0.254: 6.01,30.94 10.13,30.94 11.4,29.67 13.94,29.67 | 27.28,13.16 v54.9,13.16
PA3  (via drill 0.61 pad 1.02)
  Top 0.254: v39.03,6.49 v39.03,4.27
  Bottom 0.254: 3.47,30.94 3.47,31.57 4.1,32.21 10.45,32.21 11.72,30.94 15.85,30.94 16.48,31.57 16.48,32.21 19.02,32.21 19.66,31.57 19.66,13.79 20.29,13.16 24.74,13.16 25.37,13.16 26.01,12.52 26.01,7.13 26.64,6.49 v39.03,6.49 | v39.03,4.27 54.27,4.27 55.54,3 86.33,3 87.6,1.73
PA4  (via drill 0.61 pad 1.02)
  Top 0.254: 27.28,15.7 27.28,16.33 26.64,16.97 21.25,16.97 20.61,17.6 20.61,30.3 19.98,30.94 14.58,30.94 13.94,31.57 13.94,32.21 | v53.95,15.7 53.95,2.36 54.58,1.73 IC6.
  Bottom 0.254: 6.01,33.48 10.77,33.48 12.04,32.21 13.94,32.21 | 27.28,15.7 v53.95,15.7
PA5  (via drill 0.61 pad 1.02)
  Top 0.254: v55.85,14.43 55.85,4.9 56.49,4.27 72.36,4.27
  Bottom 0.254: 3.47,33.48 3.47,34.11 4.1,34.75 11.09,34.75 12.36,33.48 15.85,33.48 16.48,34.11 16.48,34.75 19.98,34.75 20.61,34.11 20.61,16.33 21.25,15.7 24.74,15.7 24.74,15.06 25.37,14.43 v55.85,14.43
PA6  (via drill 0.61 pad 1.02)
  Top 0.254: 27.28,18.24 27.28,18.87 26.64,19.51 22.2,19.51 21.56,20.14 21.56,32.84 20.93,33.48 14.58,33.48 13.94,34.11 13.94,34.75 | v56.81,18.24 56.81,7.44 57.44,6.81 72.36,6.81
  Bottom 0.254: J1. 11.72,36.02 12.99,34.75 13.94,34.75 | 27.28,18.24 v56.81,18.24
PA7  (via drill 0.61 pad 1.02)
  Top 0.254: v57.76,16.97 v57.76,9.35
  Bottom 0.254: 3.47,36.02 3.47,36.65 4.1,37.29 12.04,37.29 13.31,36.02 15.85,36.02 16.48,36.65 16.48,37.29 20.93,37.29 21.56,36.65 21.56,18.87 22.2,18.24 24.74,18.24 24.74,17.6 25.37,16.97 v57.76,16.97 | v57.76,9.35 72.36,9.35
PB0  (via drill 0.61 pad 1.02)
  Top 0.254: 13.31,87.45 13.31,67.45 12.67,66.82 12.67,60.78 13.31,60.15 14.9,60.15 15.53,59.51 15.53,51.26 16.17,50.62 28.55,50.62 29.18,49.99 v29.18,45.54 | v32.99,20.78 v32.99,41.73
  Bottom 0.254: 87.6,44.91 86.33,43.64 60.3,43.64 59.66,43 59.66,21.41 59.03,20.78 v32.99,20.78 J6. | 13.31,87.45 5.69,87.45 | v29.18,45.54 49.5,45.54 50.14,44.91 50.14,42.37 49.5,41.73 v32.99,41.73
PB1  (via drill 0.61 pad 1.02)
  Top 0.254: v35.22,22.05 v35.22,42.68 | v23.47,61.1 13.94,61.1 13.31,61.74 13.31,65.55 14.58,66.82 14.58,86.82 15.21,87.45 16.8,87.45
  Bottom 0.254: 24.74,20.78 24.74,21.41 25.37,22.05 v35.22,22.05 58.08,22.05 58.71,22.68 58.71,45.54 59.35,46.18 84.43,46.18 85.7,47.45 87.6,47.45 | 5.69,82.37 5.69,84.6 6.32,85.23 16.17,85.23 16.8,85.86 16.8,87.45 | v35.22,42.68 47.6,42.68 48.23,43.32 48.23,43.96 47.6,44.59 37.12,44.59 36.8,44.91 33.95,44.91 33.63,44.59 28.23,44.59 27.91,44.91 23.79,44.91 23.15,45.54 23.15,53.16 23.79,53.8 23.79,60.78 v23.47,61.1
PB2
  Bottom 0.254: 27.28,23.32 57.12,23.32 57.76,23.95 57.76,48.08 58.39,48.72 84.43,48.72 85.7,49.99 87.6,49.99
PB3
  Bottom 0.254: 24.74,23.32 24.74,23.95 25.37,24.59 56.17,24.59 56.81,25.22 56.81,49.35 57.44,49.99 72.36,49.99
PB4  (via drill 0.61 pad 1.02)
  Top 0.254: v55.85,47.76 56.17,47.45 72.36,47.45
  Bottom 0.254: 27.28,25.86 55.22,25.86 55.85,26.49 v55.85,47.76
PB5  (via drill 0.61 pad 1.02)
  Top 0.254: v54.9,44.91 72.36,44.91
  Bottom 0.254: 24.74,25.86 24.74,26.49 25.37,27.13 54.27,27.13 54.9,27.76 v54.9,44.91
PB6  (via drill 0.61 pad 1.02)
  Top 0.254: v53.95,42.37 72.36,42.37
  Bottom 0.254: 27.28,28.4 53.31,28.4 53.95,29.03 v53.95,42.37
PB7  (via drill 0.61 pad 1.02)
  Top 0.254: v53,39.83 72.36,39.83
  Bottom 0.254: 24.74,28.4 24.74,29.03 25.37,29.67 52.36,29.67 53,30.3 v53,39.83
PC0  (via drill 0.61 pad 1.02)
  Top 0.254: 27.28,30.94 27.28,30.3 26.64,29.67 22.83,29.67 22.2,30.3 22.2,40.46 21.56,41.1 11.72,41.1 11.09,40.46 11.09,29.03 11.72,28.4 14.58,28.4 15.85,27.13 16.48,27.13 | v52.04,36.02 84.43,36.02 85.7,34.75 87.6,34.75
  Bottom 0.254: 6.01,25.86 15.85,25.86 16.48,26.49 16.48,27.13 | 27.28,30.94 51.41,30.94 52.04,31.57 v52.04,36.02
PC1  (via drill 0.61 pad 1.02)
  Top 0.254: v29.82,19.51 29.82,9.03 29.18,8.4 19.66,8.4 17.75,10.3 13.31,10.3 12.67,10.93 12.67,18.87 13.31,19.51 13.94,19.51 | v50.77,38.56 84.43,38.56 85.7,37.29 87.6,37.29
  Bottom 0.254: 3.47,23.32 3.47,22.68 4.1,22.05 6.64,22.05 7.28,21.41 7.28,20.14 7.91,19.51 13.94,19.51 | v29.82,19.51 23.15,19.51 22.52,20.14 22.52,30.3 23.15,30.94 24.74,30.94 24.74,31.57 25.37,32.21 50.46,32.21 51.09,32.84 51.09,38.24 v50.77,38.56
PC2
  Top 0.254: 27.28,33.48 29.5,33.48 30.14,34.11 30.14,42.37 | 30.14,42.37 24.42,42.37 22.83,43.96 8.86,43.96 8.23,43.32 8.23,22.68 8.86,22.05 13.94,22.05 | 87.6,39.83 88.56,39.83 89.19,40.46 89.19,42.68 88.24,43.64 53.95,43.64 53.31,44.27 53.31,45.54 52.68,46.18 30.77,46.18 30.14,45.54 30.14,42.37
  Bottom 0.254: 3.47,25.86 4.1,25.86 5.37,24.59 8.55,24.59 9.18,23.95 9.18,22.68 9.82,22.05 13.94,22.05
PC3
  Top 0.254: 24.74,33.48 24.74,32.84 25.37,32.21 30.77,32.21 | 30.77,32.21 30.77,8.4 30.14,7.76 18.39,7.76 16.8,9.35 12.36,9.35 11.72,9.98 11.72,20.14 12.36,20.78 15.85,20.78 16.48,21.41 J2. | 87.6,42.37 85.7,42.37 84.43,41.1 53,41.1 52.36,41.73 52.36,43.96 51.73,44.59 32.04,44.59 31.41,43.96 31.41,32.84 30.77,32.21
PC4  (via drill 0.61 pad 1.02)
  Top 0.254: 27.28,36.02 27.28,36.65 26.64,37.29 23.47,37.29 22.83,37.92 22.83,41.42 22.2,42.05 10.77,42.05 10.13,41.42 10.13,25.22 10.77,24.59 13.94,24.59 | v48.87,36.02 48.87,33.79 49.5,33.16 67.6,33.16 69.82,30.94 83.16,30.94 83.79,30.3 83.79,29.03 84.43,28.4 88.56,28.4 89.19,29.03 89.19,31.57 88.56,32.21 87.6,32.21 87.29,32.21
  Bottom 0.254: 27.28,36.02 v48.87,36.02
PC5  (via drill 0.61 pad 1.02)
  Top 0.254: 13.94,37.29 13.94,36.65 14.58,36.02 19.98,36.02 20.61,36.65 v20.61,38.56 | v50.14,34.75 67.92,34.75 69.19,33.48 84.43,33.48 85.06,32.84 85.06,30.3 85.7,29.67 87.6,29.67
  Bottom 0.254: v20.61,38.56 21.88,38.56 22.52,37.92 22.52,36.65 23.15,36.02 24.74,36.02 24.74,35.38 25.37,34.75 v50.14,34.75
PC6  (via drill 0.61 pad 1.02)
  Top 0.254: v47.92,38.56 47.92,30.94 48.55,30.3 67.6,30.3 69.51,28.4 82.52,28.4 83.79,27.13 87.6,27.13
  Bottom 0.254: 13.94,39.83 13.94,39.19 14.58,38.56 17.75,38.56 19.02,39.83 26.64,39.83 27.28,39.19 27.28,38.56 v47.92,38.56
PC7  (via drill 0.61 pad 1.02)
  Top 0.254: 24.74,38.56 24.1,38.56 23.47,39.19 23.47,42.37 22.83,43 9.82,43 9.18,42.37 9.18,23.95 9.82,23.32 15.21,23.32 16.48,24.59 17.12,24.59 17.75,23.95 17.75,11.57 18.39,10.93 21.88,10.93 22.52,10.3 22.52,9.66 23.15,9.03 27.91,9.03 28.55,9.66 v28.55,11.89 | v85.7,10.62 85.7,23.95 86.33,24.59 87.6,24.59
  Bottom 0.254: v28.55,11.89 69.19,11.89 70.46,10.62 v85.7,10.62
PSEN  (via drill 0.61 pad 1.02)
  Top 0.254: v100.3,67.13 99.99,67.45 99.99,69.99 99.35,70.63 99.03,70.63 | v125.7,67.77 125.7,55.07 124.75,54.11 v124.75,40.78
  Bottom 0.254: v100.3,67.13 103.8,67.13 104.43,67.77 v125.7,67.77 | v124.75,40.78 124.75,39.19 125.39,38.56 128.56,38.56 129.2,37.92 129.2,33.79 128.56,33.16 105.07,33.16 104.43,32.53 98.4,32.53 97.76,31.89
PWR  (via drill 0.61 pad 1.02)
  Top 0.254: IC10.0 122.53,95.71 121.89,95.07 v121.89,85.55 122.21,85.23 122.21,77.29 121.89,76.97 v121.89,57.61 | v108.88,38.87 108.88,56.34 109.19,56.65 109.19,58.88
  Bottom 0.254: 56.81,96.98 56.81,97.93 57.44,98.57 126.34,98.57 126.97,97.93 IC10.0 | v121.89,85.55 116.81,85.55 | v108.88,38.87 109.51,38.24 112.37,38.24 113,37.61 113,37.29 | v121.89,57.61 110.46,57.61 109.19,58.88
RD  (via drill 0.61 pad 1.02)
  Top 0.254: 56.81,94.44 58.08,95.71 58.08,97.61 58.71,98.25 71.09,98.25 | 71.09,98.25 119.35,98.25 119.67,98.57 132.05,98.57 132.69,97.93 132.69,93.8 133.32,93.17 134.59,93.17 | v74.59,65.55 71.73,65.55 71.09,66.18 71.09,98.25 | v102.84,10.62 102.84,23.63 102.21,24.27 102.21,31.25 102.84,31.89 v102.84,45.86 | v89.19,49.04 89.19,51.89 88.24,52.85 88.24,58.88 87.6,59.51 80.3,59.51 79.67,60.15 79.67,64.91 79.03,65.55 78.71,65.55
  Bottom 0.254: 78.71,65.55 77.44,65.55 76.49,64.59 75.22,64.59 74.59,65.23 v74.59,65.55 | v102.84,10.62 97.13,10.62 95.86,9.35 94.59,9.35 93.95,9.98 93.95,11.25 93.32,11.89 87.6,11.89 | v102.84,45.86 102.84,49.04 102.21,49.67 97.76,49.67 97.13,49.04 96.18,49.04 95.86,48.72 89.51,48.72 v89.19,49.04
RESET  (via drill 0.61 pad 1.02)
  Top 0.254: v154.6,41.1 154.91,41.42 154.91,66.18 153.33,67.77 151.1,67.77 | v106.02,84.28 v106.02,77.93 104.75,76.66 104.75,63.96 105.07,63.64 106.02,63.64 106.34,63.32 106.34,57.93 106.65,57.61 106.65,55.39 106.02,54.75 105.38,54.75 | C9. 123.16,97.3 122.53,97.93 120.62,97.93 119.99,97.3 119.99,83.96 120.31,83.64 v120.31,81.74 v120.31,77.93 | v92.05,40.78 92.05,25.22 91.41,24.59 R14. | v101.89,40.78 v101.89,54.75
  Bottom 0.254: v154.6,41.1 148.56,41.1 | 151.1,67.77 151.1,72.21 150.47,72.85 137.77,72.85 137.13,73.48 137.13,74.12 137.13,76.02 136.5,76.66 133.96,76.66 131.42,79.2 121.58,79.2 v120.31,77.93 116.81,77.93 v106.02,77.93 | v106.02,84.28 80.62,84.28 79.98,84.91 77.13,84.91 76.17,85.86 | v120.31,81.74 124.75,81.74 125.39,82.37 126.34,82.37 IC10.5 | v92.05,40.78 92.37,40.46 94.27,40.46 94.59,40.78 v101.89,40.78 | v101.89,54.75 105.38,54.75
RXD  (via drill 0.61 pad 1.02)
  Top 0.254: v81.57,79.2 81.57,73.8 80.94,73.16 78.71,73.16 | v100.62,79.2 100.62,83.64 101.26,84.28 102.53,84.28 103.16,84.91 103.16,86.18 104.43,87.45 104.43,90.31 105.07,90.94 106.02,90.94 106.65,91.58 v106.65,94.12
  Bottom 0.254: v81.57,79.2 v100.62,79.2 | v106.65,94.12 106.65,94.44 107.29,95.07 126.02,95.07 126.66,94.44 138.4,94.44 139.04,93.8 139.04,88.72 138.4,88.09 137.13,88.09
TXD  (via drill 0.61 pad 1.02)
  Top 0.254: v82.52,81.1 82.52,72.53 81.89,71.9 77.44,71.9 76.17,70.63 | v96.49,81.1 97.45,81.1 98.08,81.74 98.08,84.28 98.72,84.91 101.89,84.91 102.53,85.55 102.53,86.82 103.8,88.09 103.8,91.26 v104.43,91.9
  Bottom 0.254: v82.52,81.1 v96.49,81.1 | v104.43,91.9 136.5,91.9 137.13,91.26 137.13,90.63
VAGND  (via drill 0.61 pad 1.02)
  Top 0.254: v74.59,92.21 74.59,83.96 75.22,83.33 76.17,83.33
  Bottom 0.254: v74.59,92.21 53,92.21 52.36,92.85 52.36,96.34 53,96.98 54.27,96.98
VAREF  (via drill 0.61 pad 1.02)
  Top 0.254: v54.27,87.77 54.27,94.44
  Bottom 0.254: v54.27,87.77 78.08,87.77 78.71,87.13 78.71,85.86
VCC  (via drill 0.61 pad 1.02)
  Top 0.254: v91.73,54.43 91.41,54.75 | 111.1,3 111.73,3.63
  Top 0.406: v52.04,37.29 72.36,37.29 | v22.2,65.86 26.33,65.86 26.96,66.5 26.96,73.8 | v114.27,56.65 JP2. | 134.59,80.47 IC11. | 146.66,43.64 146.66,73.48 R2. 148.56,74.12 149.2,74.75 149.2,87.45 149.83,88.09 C4. | 146.66,43.64 T1. | v145.71,24.59 146.02,24.91 146.02,40.15 146.66,40.78 146.66,43.64 | v110.46,78.88 110.46,72.85 110.46,64.59 110.78,64.28 110.78,60.47 110.46,60.15 110.46,56.97 109.83,56.34 109.83,55.7 IC3. 110.46,39.83 110.46,38.87 109.19,37.61 109.19,26.18 111.73,23.63 111.73,21.73 110.46,20.46 IC4. 110.46,17.29 111.73,16.01 111.73,3.63 | 90.14,10.62 90.78,9.98 90.78,2.36 91.41,1.73 IC2. 98.72,1.73 99.35,2.36 99.35,3 | 99.35,3 99.35,28.72 98.72,29.35 IC8. 95.86,29.35 95.22,29.98 95.22,32.53 95.54,32.84 v95.54,39.51 95.54,46.5 95.22,46.81 v95.22,49.99 | v91.73,54.43 93,53.16 C11. | 91.41,54.75 91.41,63 90.14,64.28 90.14,66.5 90.78,67.13 90.78,74.12 91.41,74.75 IC1. | 99.35,3 111.1,3
  Bottom 0.254: R5. 13.63,97.61 | R9. 22.52,80.15 | v110.46,78.88 110.78,78.56
  Bottom 0.406: 3.47,20.78 3.47,17.6 4.1,16.97 13.94,16.97 13.94,7.44 | 13.94,7.44 15.85,7.44 | 16.48,41.1 16.48,39.83 | 16.48,41.1 2.2,41.1 1.56,40.46 1.56,16.01 2.2,15.38 3.47,15.38 4.1,14.74 4.1,3.95 4.74,3.31 13.31,3.31 13.94,3.95 13.94,7.44 | v52.04,37.29 52.04,38.87 51.73,39.19 51.73,39.83 51.09,40.46 27.91,40.46 27.28,41.1 24.74,41.1 19.66,41.1 | 5.69,92.53 5.69,96.98 6.32,97.61 R5. R4. 16.8,90.31 17.44,89.68 20.29,89.68 20.93,89.04 20.93,80.15 | 20.93,80.15 R9. 25.06,80.15 25.69,79.52 C14. 25.69,74.44 26.33,73.8 26.96,73.8 | 16.48,41.1 19.66,41.1 | 20.93,80.15 R8. | v114.27,56.65 113.96,56.97 110.46,56.97 109.83,56.34 109.83,55.7 IC3. | 134.59,80.47 129.2,80.47 127.93,81.74 125.7,81.74 124.43,80.47 123.8,79.83 118.72,79.83 118.08,79.2 116.18,79.2 115.54,78.56 110.78,78.56 | v145.71,24.59 148.56,24.59 | IC11. 142.21,77.93 142.85,77.29 142.85,74.75 143.48,74.12 R2. | v91.73,54.43 81.89,54.43 81.25,55.07 72.68,55.07 72.05,54.43 72.05,53.8 | v95.22,49.99 C11. | v95.54,39.51 90.14,39.51 88.56,41.1 77.76,41.1 77.13,40.46 77.13,37.92 76.49,37.29 72.36,37.29 | v22.2,65.86 20.29,65.86 19.66,65.23 19.66,56.02 19.66,41.1
VN  (via drill 0.61 pad 1.02)
  Top 0.254: 125.7,37.29 126.66,36.33 126.66,20.14 126.02,19.51 125.7,19.51 | v99.67,38.24 99.67,37.61 99.03,36.97 97.76,36.97
  Bottom 0.254: v99.67,38.24 106.34,38.24 108.56,36.02 124.43,36.02 125.7,37.29
VPD  (via drill 0.61 pad 1.02)
  Top 0.254: v86.33,69.04 86.33,85.86 | 124.43,77.93 125.07,77.93 126.97,76.02 IC10.8 | v110.78,26.49 110.46,26.81 IC5. 111.42,38.24 111.42,54.75 113,56.34 v113,69.04 113,72.85 v113,76.66 | v155.87,25.22 155.55,24.91 155.55,2.36 154.91,1.73
  Bottom 0.254: v86.33,69.04 106.65,69.04 v113,69.04 | 94.91,26.18 91.41,26.18 90.14,27.45 | 94.91,26.18 94.59,26.18 | 94.91,26.18 98.4,26.18 98.72,26.49 v110.78,26.49 148.88,26.49 150.15,25.22 v155.87,25.22 | v113,76.66 117.13,76.66 117.45,76.97 123.48,76.97 124.43,77.93
WR  (via drill 0.61 pad 1.02)
  Top 0.254: v81.57,64.28 82.52,65.23 82.52,66.82 83.16,67.45 89.19,67.45 89.83,68.08 89.83,91.9 90.46,92.53 102.53,92.53 103.48,93.49 103.48,95.07 104.11,95.71 108.56,95.71 109.83,94.44 118.72,94.44 119.35,93.8 v119.35,83.01 119.35,77.29 119.99,76.66 v119.99,72.21 | v84.75,11.57 v84.75,23 | v129.83,25.54 v129.83,72.21
  Bottom 0.254: v81.57,64.28 79.35,64.28 78.71,63.64 78.71,63 | v119.35,83.01 116.81,83.01 | v84.75,11.57 84.43,11.89 72.36,11.89 | v84.75,23 85.06,23.32 99.35,23.32 99.99,23.95 99.99,25.22 100.62,25.86 107.92,25.86 108.24,25.54 v129.83,25.54 | v129.83,72.21 v119.99,72.21

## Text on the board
Top: 1 | 1 | VCC | Port4 | Port5 | 1 | PB0 | INT1 | DCF-77 | PB1 | 5V | 6.5V | Port6 | GND | 1 | PWR | VCC | 1 | Port1 | PIO | 1 | Port0 | 1 | 1 | 1 | 1 | Pio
